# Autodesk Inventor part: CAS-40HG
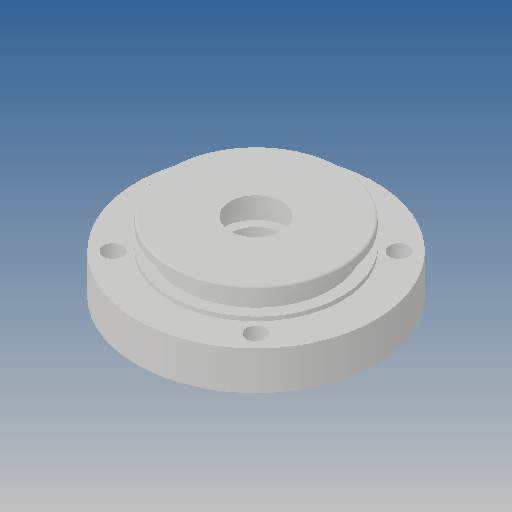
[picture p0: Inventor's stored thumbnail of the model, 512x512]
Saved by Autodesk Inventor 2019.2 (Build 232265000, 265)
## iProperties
Created: 2009-09
Part Number: CAS-40HG
Material: Ogólny
Document SubType Name: Modeling
Designer: CADENGINEERING4
Density: 1 g/cm^3
Appearance: Domyślna
Author: CADENGINEERING4
Revision Number: 1LAST_VERSION
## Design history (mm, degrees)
feature "Baza1"
node "Bryła1"
